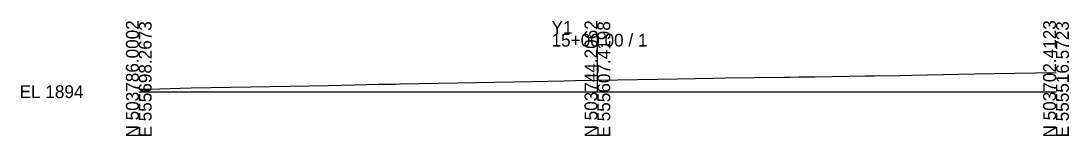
# Model space of a CAD drawing. Extents: x -26 to 203, y -10 to 5015.
# Drawn here: x -25.7 to 202.8, y 4990.3 to 5015.5 of the extents above; entities that cross this region are included whole.
import ezdxf

# ---------------------------------------------------------------- set-up
doc = ezdxf.new("R2010")
doc.units = 0
doc.layers.add('Exist Cross Section Cell', color=7, linetype='Continuous')
doc.layers.add('Exist XS Ground Line', color=7, linetype='Continuous')

msp = doc.modelspace()

# ---------------------------------------------------------------- linework, layer by layer
at = {"layer": 'Exist Cross Section Cell'}
for p, q in [((100, 5000), (100, 5012.66)), ((0, 5000), (100, 5000)), ((100, 5000), (200, 5000))]:
    msp.add_line(p, q, dxfattribs=at)
at = {"layer": 'Exist XS Ground Line'}
for p, q in [((100, 5002.51), (117.43, 5002.82)), ((117.43, 5002.82), (125.2, 5002.96)), ((125.2, 5002.96), (127.87, 5003)), ((127.87, 5003), (140.67, 5003.16)), ((140.67, 5003.16), (142.04, 5003.21)), ((142.04, 5003.21), (143.99, 5003.23)), ((143.99, 5003.23), (147.43, 5003.28)), ((147.43, 5003.28), (154.93, 5003.41)), ((154.93, 5003.41), (158.38, 5003.46)), ((158.38, 5003.46), (160.39, 5003.48)), ((160.39, 5003.48), (165.98, 5003.57)), ((165.98, 5003.57), (168.58, 5003.62)), ((168.58, 5003.62), (182.26, 5003.89)), ((182.26, 5003.89), (190.99, 5004.04)), ((190.99, 5004.04), (200, 5004.22)), ((0, 5000.54), (2.44, 5000.58)), ((2.44, 5000.58), (9.02, 5000.77)), ((9.02, 5000.77), (11.41, 5000.82)), ((11.41, 5000.82), (32.93, 5001.24)), ((32.93, 5001.24), (41.31, 5001.39)), ((41.31, 5001.39), (47.08, 5001.51)), ((47.08, 5001.51), (49.72, 5001.56)), ((49.72, 5001.56), (52.16, 5001.61)), ((52.16, 5001.61), (54.79, 5001.65)), ((54.79, 5001.65), (55.91, 5001.68)), ((55.91, 5001.68), (56.97, 5001.69)), ((56.97, 5001.69), (65.38, 5001.86)), ((65.38, 5001.86), (85.76, 5002.25)), ((85.76, 5002.25), (92.74, 5002.38)), ((92.74, 5002.38), (95.2, 5002.42)), ((95.2, 5002.42), (100, 5002.51))]:
    msp.add_line(p, q, dxfattribs=at)

# ---------------------------------------------------------------- texts
at = {"layer": 'Exist Cross Section Cell'}
for s, p in [('N 503786.0002', (0, 4990)), ('E 555698.2673', (2.8, 4990)), ('N 503744.2062', (100, 4990)), ('E 555607.4198', (102.8, 4990)), ('N 503702.4123', (200, 4990)), ('E 555516.5723', (202.8, 4990))]:
    msp.add_text(s, height=2.8, rotation=90, dxfattribs=at).set_placement(p)
for s, p in [('Y1', (90, 5012.66)), ('15+00.00 / 1', (90, 5009.86)), ('EL 1894', (-26, 4998.6))]:
    msp.add_text(s, height=2.8, dxfattribs=at).set_placement(p)

doc.saveas('drawing.dxf')
